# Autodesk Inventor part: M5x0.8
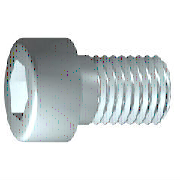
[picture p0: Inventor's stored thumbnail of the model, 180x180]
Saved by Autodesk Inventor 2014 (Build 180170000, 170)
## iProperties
IsCustomPart: 0
Manager: KYOUNG IL JANG
Company: 한국ATC센터
Created: 2009-02
Part Number: M5x0.8
Material: Steel, Mild
Description: 6각머리 태핑 나사
Document SubType Name: Modeling
Standard: KS B 1003
Standards Organization: KS
Language: ko-KR
Size Designation: M 5 x 20
Categories: <MemberInstance><Categories><Category DisplayName="조임쇠" InternalName="e4da775c-781d-43d5-af7c-5136215cf5a6" Mnemonic="FSTN"><Category DisplayName="볼트" InternalN
Density: 1 g/cm^3
Checked By: KYOUNG IL JANG
Vendor: CBT Solutions
Designer: KYOUNG IL JANG
Appearance: Steel
Author: KYOUNG IL JANG
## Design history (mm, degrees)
revolve "본체" stored, may be unused: angle "d10" = 90 deg
sketch "스케치2"
  geometry: L1 (0, -5.95)-(0, 5.95) reference; L2 (-5.95, 0)-(5.95, 0) reference; L3 (2.309, 0)-(1.155, -2); L4 (1.155, -2)-(-1.155, -2); L5 (-1.155, -2)-(-2.309, 0); L6 (-2.309, 0)-(-1.155, 2); L7 (-1.155, 2)-(1.155, 2); L8 (1.155, 2)-(2.309, 0); 2 further points
  constraints: 12 end point, 1 coincident, 1 horizontal alignment, 1 point on line, 12 other
extrude "슬롯" join sketch "스케치2" stored distance "d11" = 10; taper "d12" = 0 deg
workplane "Work Plane1"
fillet "Fillet2" dims "d30" = 0.1 (= R)
body "Solid1"
fillet "모깎기1" dims "d17" = 0.5 (= RR)
feature "스레드" dims "d13" = 18 (= GEL), "d14" = 0
chamfer "모따기1" distance "d15" = 0.49076 (= -0.5 x SPD + 0.5 x GD); stored, may be unused: second distance "d16" = 0.49076 (= GUL), angle "d27" = 45 deg
sketch "스케치1"
  geometry: L1 (-1.167, 0)-(20, 0); L2 (20, 0)-(20, 2.5); L3 (20, 2.5)-(2, 2.5); L4 (2, 2.5)-(1.509, 2.5); L5 (1.509, 2.5)-(0, 2.5); L6 (0, 2.5)-(0, 4.25); L7 (0, 4.25)-(-5, 4.25); L8 (-5, 4.25)-(-5, 2.309); L9 (-5, 2.309)-(-2.5, 2.309); L10 (-2.5, 2.309)-(-1.167, 0); L11 (-10, 0)-(25, 0) reference; L12 (0, -0.85)-(0, 5.1) reference; L13 (2, 2.5)-(0, 2.5)
  constraints: 22 end point, 6 parallel, 2 collinear, 2 perpendicular, 1 horizontal, 1 point on line
  dimensions: "d1" = 18 distance from line of L3.end L2 (= GEL); "d2" = 0.49086 distance of L4.end L3.end (computed from GAL); "d3" = 5 distance between parallel lines of L8 L6 (= KOH); "d4" = 2.5 distance of L8.end L9.end (= INTI); "d5" = 60 deg angle of L10 L1; "d6" = 5 diameter of L3 L1 (= GD); "d7" = 5 diameter of L5 L1 (= BDM); "d8" = 4.6188 diameter of L9 L1 (= 1.1547 x SW); "d9" = 8.5 diameter of L7 L1 (= KOD); "d26" = 20 distance between parallel lines of L12 L2 (= NLG)
other parameters: "GD" = 5 (= NND) [user parameter; used in 2 equation terms], "NLG" = 20 [user parameter; used in 1 equation term], "GEL" = 18 [user parameter; used in 2 equation terms], "KOD" = 8.5 [user parameter; used in 1 equation term], "KOH" = 5 [user parameter; used in 1 equation term], "INTI" = 2.5 [user parameter; used in 1 equation term], "GAL" = 0.49076 (= 0.61345 x PTC) [user parameter; used in 1 equation term], "GUL" = 0.49076 (= 0.61345 x PTC) [user parameter; used in 1 equation term], "BDM" = 5 (= NND) [user parameter; used in 1 equation term], "SW" = 4 [user parameter; used in 2 equation terms], "RR" = 0.5 [user parameter; used in 1 equation term], "SPD" = 4.01848 (= NND - 1.2269 x PTC) [user parameter; used in 1 equation term], "d19" = 0, "d28" = 0, "d29" = 0, "R" = 0.1 [user parameter; used in 1 equation term], "PHH" = 0.2 [user parameter], "GD1" = 4.01848 (= THREADDIA - 1.2269 x PTC) [user parameter], "THREADDIA" = 5 [user parameter; used in 1 equation term], "FAWI" = 45 deg [user parameter], "TPU" = 12.5 (computed from PTC) [user parameter], "PTC" = 0.8 [user parameter; used in 5 equation terms], "NND" = 5 [user parameter; used in 3 equation terms], "TOA" = 30 deg [user parameter], "E0" = 4.62 (= 1.155 x SW) [user parameter]
